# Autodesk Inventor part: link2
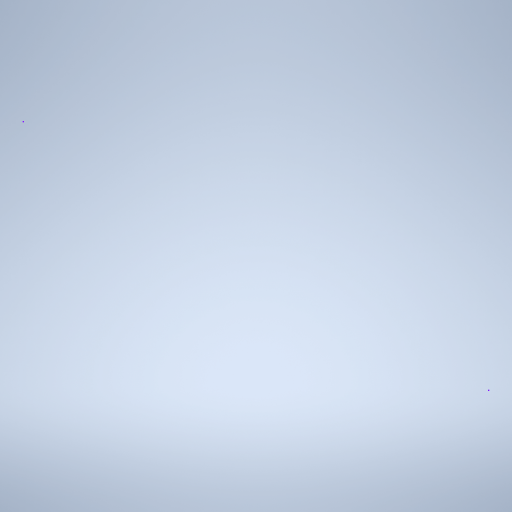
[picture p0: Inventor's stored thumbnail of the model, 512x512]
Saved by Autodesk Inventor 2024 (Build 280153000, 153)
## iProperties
Created: 2023-10
Part Number: link2
Material: Generic
Document SubType Name: Modeling
Designer: ESTUDIANTE
Density: 1 g/cm^3
Appearance: Default
Author: ESTUDIANTE
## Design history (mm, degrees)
sketch "Sketch1"
  geometry: 2 further points
  constraints: 1 horizontal alignment
